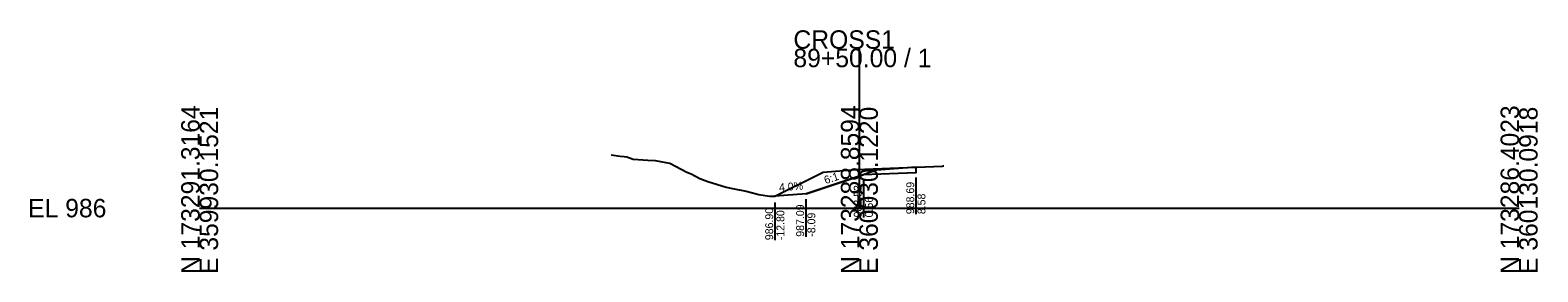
# Model space of a CAD drawing. Extents: x -26 to 1403, y -10 to 11027.
# Drawn here: x -25.7 to 202.8, y 4490.3 to 4527 of the extents above; entities that cross this region are included whole.
import ezdxf

# ---------------------------------------------------------------- set-up
doc = ezdxf.new("R2010")
doc.units = 0
for name, color, linetype in [('Default', 7, 'Continuous'), ('P_E_XS_Ground', 7, 'Continuous'), ('P_XS', 7, 'Continuous'), ('P_XS_EAR_CommonGrnd', 7, 'Continuous'), ('P_XS_Lane', 7, 'Continuous'), ('P_XS_Rock', 7, 'Continuous')]:
    doc.layers.add(name, color=color, linetype=linetype)

msp = doc.modelspace()

# ---------------------------------------------------------------- linework, layer by layer
at = {"layer": 'Default'}
for p, q in [((100, 4500), (100, 4524.21)), ((0, 4500), (100, 4500)), ((100, 4500), (200, 4500))]:
    msp.add_line(p, q, dxfattribs=at)
at = {"layer": 'P_E_XS_Ground'}
for p, q in [((62.39, 4508.07), (63.72, 4507.9)), ((63.72, 4507.9), (64.36, 4507.86)), ((64.36, 4507.86), (64.76, 4507.78)), ((64.76, 4507.78), (65.73, 4507.45)), ((65.73, 4507.45), (67.92, 4507.29)), ((67.92, 4507.29), (69.04, 4507.21)), ((69.04, 4507.21), (70.64, 4506.93)), ((70.64, 4506.93), (71.29, 4506.83)), ((71.29, 4506.83), (73.83, 4505.45)), ((73.83, 4505.45), (74.51, 4505.22)), ((74.51, 4505.22), (75.82, 4504.48)), ((75.82, 4504.48), (77.03, 4504.04)), ((87.2, 4501.81), (94.5, 4505.45)), ((94.5, 4505.45), (99.5, 4505.85)), ((99.5, 4505.85), (112.58, 4506.38)), ((112.58, 4506.41), (112.78, 4506.42)), ((112.58, 4506.38), (112.58, 4506.41)), ((77.03, 4504.04), (79.81, 4503.16)), ((79.81, 4503.16), (81.01, 4502.94)), ((81.01, 4502.94), (82.84, 4502.6)), ((82.84, 4502.6), (84.78, 4502.05)), ((84.78, 4502.05), (86.37, 4501.81)), ((86.37, 4501.81), (87.2, 4501.81))]:
    msp.add_line(p, q, dxfattribs=at)
at = {"layer": 'P_XS'}
for p, q in [((102.58, 4505.74), (100.56, 4505.06)), ((108.58, 4506.22), (102.58, 4505.74))]:
    msp.add_line(p, q, dxfattribs=at)
at = {"layer": 'P_XS_EAR_CommonGrnd'}
msp.add_lwpolyline([(94.5, 4505.45), (99.5, 4505.85), (108.58, 4506.22), (108.58, 4505.38), (100.56, 4505.06), (91.91, 4502.18), (87.2, 4501.81)], close=True, dxfattribs=at)
at = {"layer": 'P_XS_Lane'}
for p, q in [((91.91, 4502.18), (100.56, 4505.06)), ((108.58, 4505.38), (100.56, 4505.06)), ((108.58, 4506.22), (108.58, 4505.38)), ((112.58, 4506.38), (112.58, 4506.41)), ((91.91, 4502.18), (87.2, 4501.81))]:
    msp.add_line(p, q, dxfattribs=at)
at = {"layer": 'P_XS_Rock'}
for p, q in [((108.56, 4504.67), (108.56, 4499.07)), ((100.6, 4504.19), (100.6, 4498.59)), ((87.18, 4500.85), (87.18, 4495.13)), ((91.87, 4501.34), (91.87, 4495.65))]:
    msp.add_line(p, q, dxfattribs=at)

# ---------------------------------------------------------------- texts
at = {"layer": 'Default'}
for s, p in [('CROSS1', (90, 4524.21)), ('89+50.00 / 1', (90, 4521.41)), ('EL 986', (-26, 4498.6))]:
    msp.add_text(s, height=2.8, dxfattribs=at).set_placement(p)
for s, p in [('N 173291.3164', (0, 4490)), ('E 359930.1521', (2.8, 4490)), ('N 173288.8594', (100, 4490)), ('E 360030.1220', (102.8, 4490)), ('N 173286.4023', (200, 4490)), ('E 360130.0918', (202.8, 4490))]:
    msp.add_text(s, height=2.8, rotation=90, dxfattribs=at).set_placement(p)
at = {"layer": 'P_XS_Rock'}
for s, rotation, p in [('6:1', 18.4349, (94.88, 4503.64)), ('4.0%', 4.5739, (87.86, 4502.54)), ('988.53', 90, (100.35, 4498.59)), ('988.69', 90, (108.31, 4499.08)), ('8.58', 90, (110.01, 4499.08)), ('986.90', 90, (86.93, 4495.13)), ('987.09', 90, (91.62, 4495.65)), ('0.56', 90, (102.05, 4498.59)), ('-12.80', 90, (88.63, 4495.13)), ('-8.09', 90, (93.32, 4495.65))]:
    msp.add_text(s, height=1.2, rotation=rotation, dxfattribs=at).set_placement(p)

doc.saveas('drawing.dxf')
